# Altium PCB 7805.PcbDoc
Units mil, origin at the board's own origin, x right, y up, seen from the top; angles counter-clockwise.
Board outline 6000 x 4000 mil, 2 copper layers (Top Layer, Bottom Layer); 11 components, 10 nets, 36 pads, 0 vias.
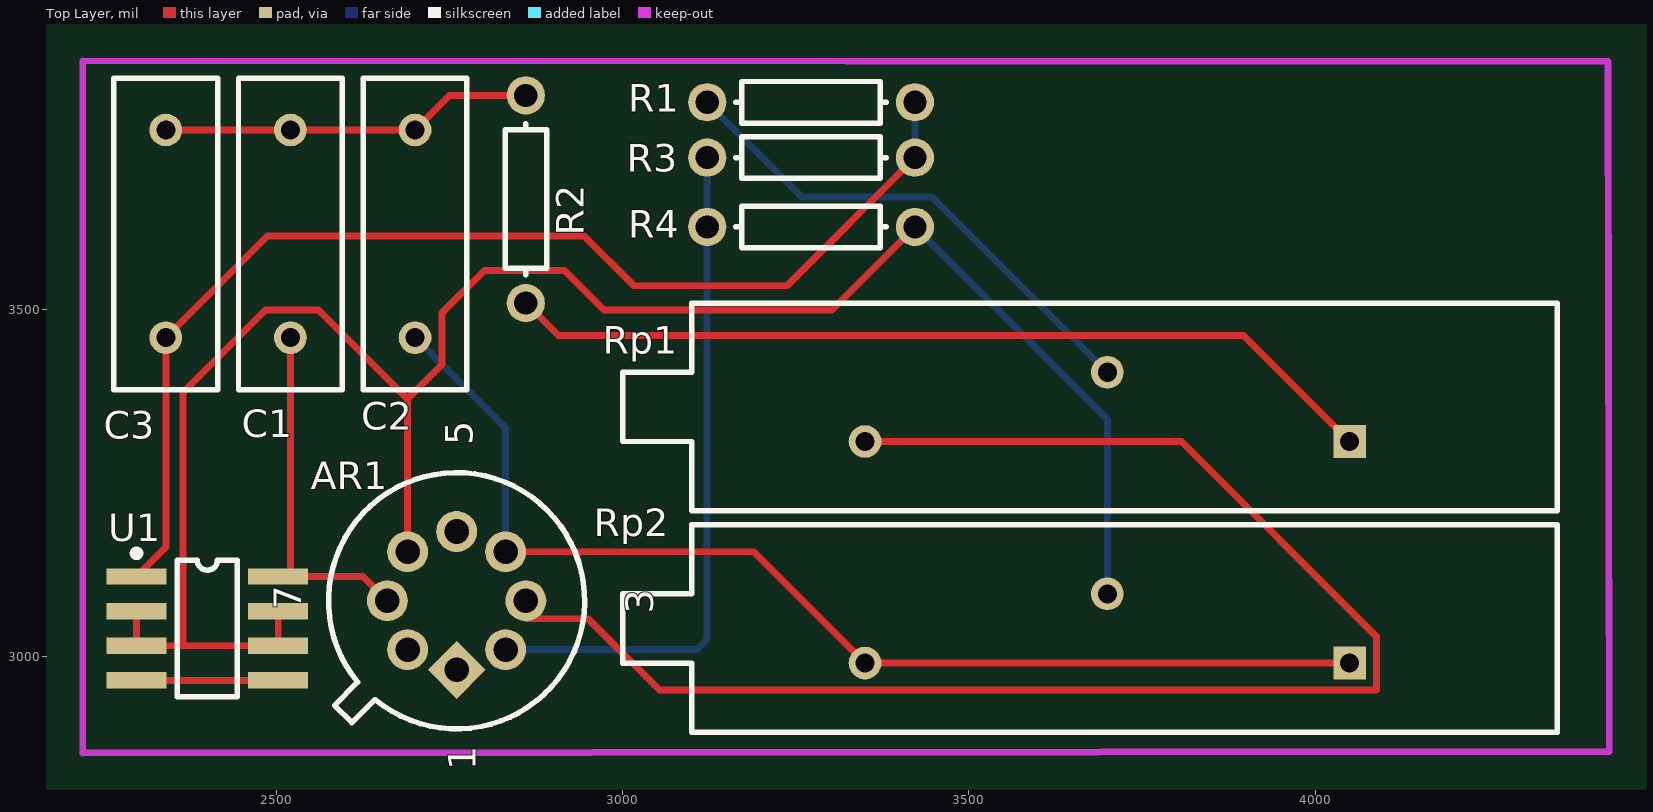
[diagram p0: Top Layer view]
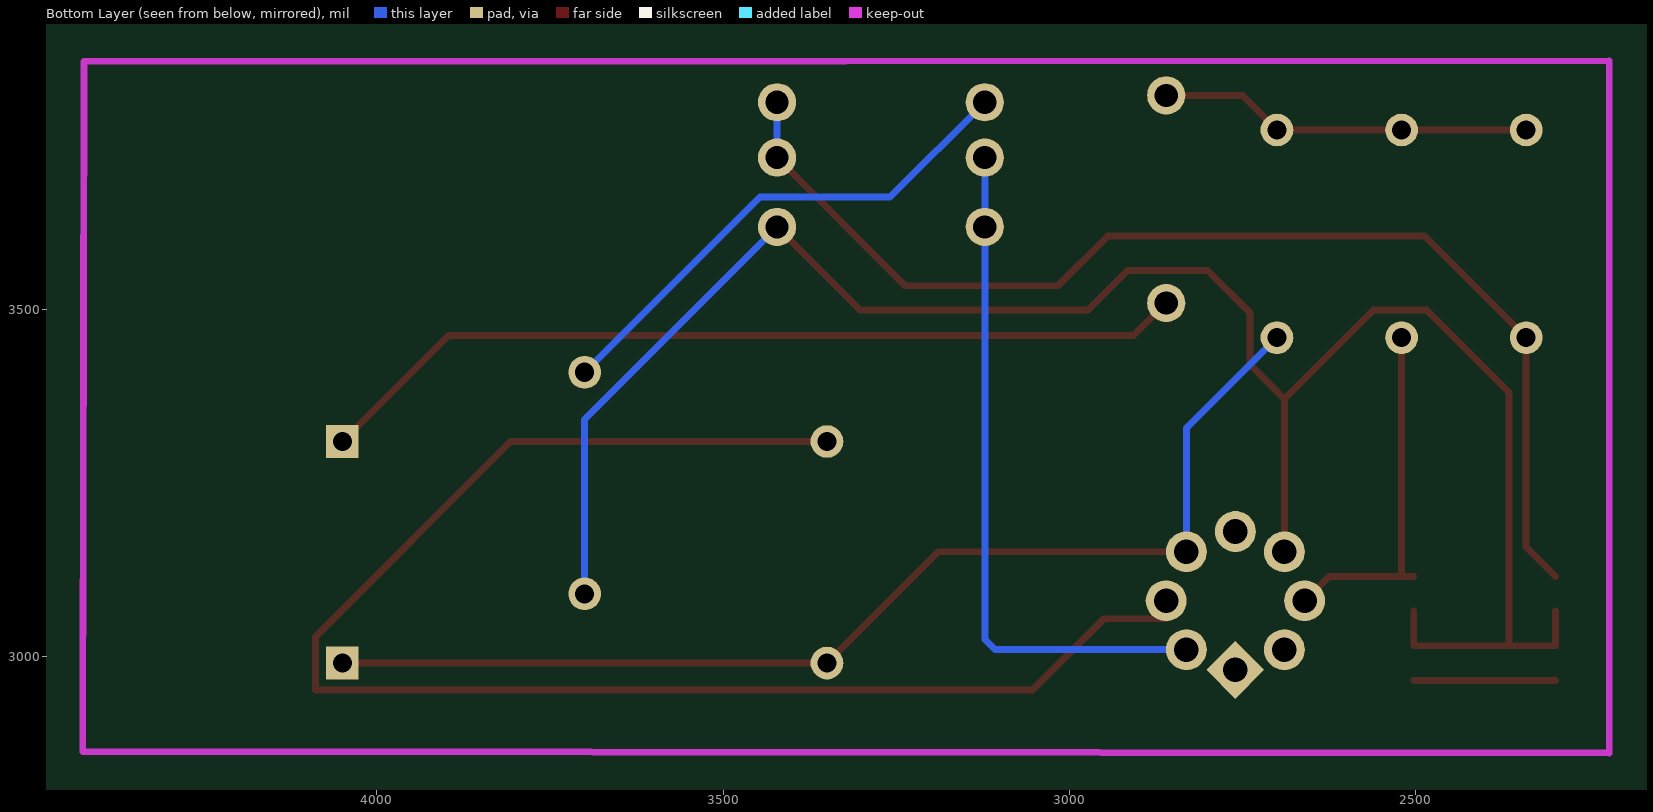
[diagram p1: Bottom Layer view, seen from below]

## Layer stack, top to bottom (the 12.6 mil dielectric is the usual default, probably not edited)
Top Layer: signal copper 1.4
Dielectric: dielectric 12.6, FR-4, Dk 4.8
Bottom Layer: signal copper 1.4

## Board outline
1000,1000 7000,1000 7000,5000 1000,5000

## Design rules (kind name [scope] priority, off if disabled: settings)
Clearance [All] p1: gap=10
ComponentClearance [All] p1: gap=10 collisioncheckmode=0
PolygonConnect [All] p1: connectstyle=Relief reliefconductorwidth=10 reliefentries=4 polygonreliefangle="90 Angle"
RoutingLayers [All] p1: top layer=Horizontal bottom layer=Vertical
RoutingVias [All] p1: holewidth=28 width=50 viastyle="Through Hole" minholewidth=28 minwidth=50 maxholewidth=28 maxwidth=50
SolderMaskExpansion [All] p1: expansion=4
TestPointUsage [All] p1: valid=0 allowmultiple=FALSE
Testpoint [All] p1: side=15 testpointundercomponent=TRUE minsize=40 maxsize=100 preferedsize=60 minholesize=0 maxholesize=40 preferedholesize=32 testpointgrid=1 style=1023 order=-539222988
Width [All] p1: maxlimit=10 minlimit=10 preferedwidth=10
16 further rules are at their usual default settings.

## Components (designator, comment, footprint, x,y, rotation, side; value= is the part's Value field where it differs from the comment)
AR1 "Op Amp" CAN-8/D9.4 2760,3080 r90 top
C1 "0.22μF" RAD-0.3 2520,3760 r270 top
C2 "0.22μF" RAD-0.3 2700,3760 r270 top
C3 "Cap" RAD-0.3 2340,3760 r270 top
R1 "Res1" AXIAL-0.3 3272,3800 r0 top
R2 "Res1" AXIAL-0.3 2860,3660 r270 top
R3 "Res1" AXIAL-0.3 3272,3720 r0 top
R4 "Res1" AXIAL-0.3 3272,3620 r180 top
Rp1 "Res Tap" VR3 3700,3360 r180 top
Rp2 "Res Tap" VR3 3700,3040 r180 top
U1 "L78L05ABD" SO-G8 2400,3040 r270 top

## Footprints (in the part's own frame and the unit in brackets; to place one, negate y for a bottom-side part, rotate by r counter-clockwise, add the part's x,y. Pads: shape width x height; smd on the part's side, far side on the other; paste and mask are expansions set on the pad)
AXIAL-0.3 [mm]
  round 1.4 hole 0.85: 1(-3.81,0) 2(3.81,0)
  silkscreen extent -2.77,-0.76 2.77,0.76
CAN-8/D9.4 [mm]
  rect 1.5x1.5 hole 0.9 rot 45: 1(-2.54,0)
  round 1.5 hole 0.9: 2(-1.796,-1.796) 3(0,-2.54) 4(1.796,-1.796) 5(2.54,0) 6(1.796,1.796) 7(0,2.54) 8(-1.796,1.796)
  silkscreen extent -4.7,-4.7 4.7,4.7
RAD-0.3 [mm]
  round 1.2 hole 0.7: 1(0,0) 2(7.62,0)
  silkscreen extent -1.91,-1.91 9.53,1.91
SO-G8 [mm]
  rect 0.6x2.2 smd: 1(-1.905,-2.6) 2(-0.635,-2.6) 3(0.635,-2.6) 4(1.905,-2.6) 5(1.905,2.6) 6(0.635,2.6) 7(-0.635,2.6) 8(-1.905,2.6)
  silkscreen extent -2.88,-2.72 2.5,1.1
VR3 [mm]
  rect 1.2x1.2 hole 0.7: 1(-8.89,1.27)
  round 1.2 hole 0.7: 2(0,-1.27) 3(8.89,1.27)
  silkscreen extent -16.51,-3.81 17.78,3.81

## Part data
AR1: "FET Operational Amplifier"
C1 C2: library part Cap, "Capacitor"
C3: "Capacitor"
R1 R2 R3 R4: "Resistor"
Rp1 Rp2: "Tapped Resistor"
U1: "Positive Voltage Regulator"

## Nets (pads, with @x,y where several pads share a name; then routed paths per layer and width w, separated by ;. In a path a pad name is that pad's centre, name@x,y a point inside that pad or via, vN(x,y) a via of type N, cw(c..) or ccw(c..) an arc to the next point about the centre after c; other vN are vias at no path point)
GND: C1.1 C2.1 C3.1 R2.1 | length 540.7
  Top Layer w10: C3.1 C1.1 C2.1 2750,3810 R2.1
NetAR1_2: AR1.2 R3.1 R4.2 | length 993.2
  Bottom Layer w10: AR1.2 3107,3009.29 3122,3024.29 R4.2 R3.1
NetAR1_3: AR1.3 Rp1.3 | length 2230.5
  Top Layer w10: AR1.3 2860,3054 2950,3054 3053,2951 4089,2951 4089,3028 3807,3310 Rp1.3
NetAR1_4: AR1.4 C2.2 Rp2.1 Rp2.3 | length 1649.3
  Top Layer w10: AR1.4 3189.29,3150.71 Rp2.3 Rp2.1
  Bottom Layer w10: C2.2 2830.71,3329.29 AR1.4
NetAR1_6: AR1.6 R4.1 Rp2.2 U1.2 U1.3 U1.6 U1.7 | length 2890.1
  Top Layer w10: U1.2 U1.3 2365,3015 ; U1.7 U1.6 2365,3015 ; AR1.6 2689.29,3371 2689.14,3371.14 ; R4.1 3302,3500 2973,3500 2916,3557 2800,3557 2739,3496 2739,3421 2689.14,3371.14 ; 2365,3015 2365,3380.71 2484.29,3500 2560.29,3500 2689.14,3371.14
  Bottom Layer w10: R4.1 3700,3342 Rp2.2
NetAR1_7: AR1.7 C1.2 U1.8 | length 517.1
  Top Layer w10: U1.8 U1.8@2520,3115 ; C1.2 U1.8@2520,3115 ; AR1.7 2625,3115 U1.8@2520,3115
NetC3_2: C3.2 R1.2 R3.2 U1.1 | length 1691.9
  Top Layer w10: U1.1 2340,3157.36 C3.2 2487,3607 2944,3607 3016,3535 3237,3535 R3.2
  Bottom Layer w10: R3.2 R1.2
NetR1_1: R1.1 Rp1.2 | length 739.5
  Bottom Layer w10: R1.1 3259,3663 3447,3663 Rp1.2
NetR2_2: R2.2 Rp1.1 | length 1272.8
  Top Layer w10: R2.2 2907,3463 3897,3463 Rp1.1
NetU1_4: U1.4 U1.5 | length 204.7
  Top Layer w10: U1.4 U1.5
pads on no net: AR1.1 AR1.5 AR1.8

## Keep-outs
Keep-Out Layer:
  lines w10: 2220,2860 2220,3860 4423,3859 4425,2862 2220,2860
